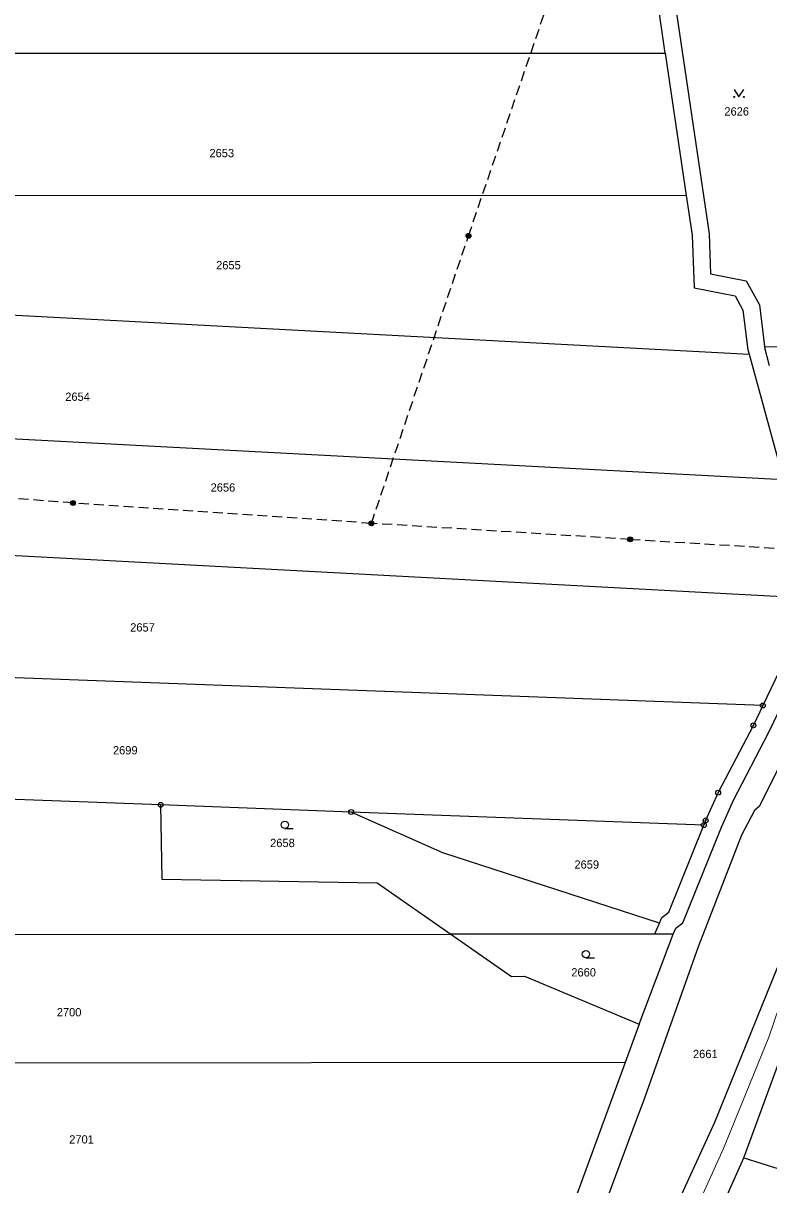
# Model space of a CAD drawing. Extents: x -606517 to -602431, y -1183120 to -1179397.
# Drawn here: x -605722.9 to -605569.9, y -1181000.2 to -1180761.6 of the extents above; entities that cross this region are included whole.
import ezdxf

# ---------------------------------------------------------------- set-up
doc = ezdxf.new("R2010")
doc.units = 0
doc.header["$LTSCALE"] = 0.68
doc.linetypes.add('MEDIUM_DASHED', pattern=[4.5, 3, -1.5])
for name, color, linetype, lineweight in [('1', 7, 'Continuous', 25), ('3', 7, 'Continuous', 25), ('4', 7, 'Continuous', 13), ('6', 7, 'Continuous', 25), ('8', 7, 'Continuous', 25)]:
    doc.layers.add(name, color=color, linetype=linetype, lineweight=lineweight)
doc.layers.add('2', color=7, linetype='Continuous')

msp = doc.modelspace()

# ---------------------------------------------------------------- linework, layer by layer
at = {"layer": '1'}
for p, q in [((-605591.11, -1180767.77), (-605594.1, -1180747.43)), ((-605590.7, -1180746.5), (-605582.12, -1180804.85)), ((-605748.69, -1180767.72), (-605591.11, -1180767.77)), ((-605591.11, -1180767.77), (-605586.81, -1180796.99)), ((-605751.61, -1180796.94), (-605586.81, -1180796.99)), ((-605586.81, -1180796.99), (-605585.61, -1180805.17)), ((-605582.12, -1180804.85), (-605581.81, -1180813.05)), ((-605585.61, -1180805.17), (-605585.2, -1180815.94)), ((-605581.81, -1180813.05), (-605574.5, -1180814.52)), ((-605574.5, -1180814.52), (-605571.79, -1180819.43)), ((-605585.2, -1180815.94), (-605576.78, -1180817.63)), ((-605576.78, -1180817.63), (-605575.18, -1180820.53)), ((-605754.37, -1180819.97), (-605573.91, -1180829.6)), ((-605575.18, -1180820.53), (-605574.16, -1180828.69)), ((-605571.79, -1180819.43), (-605570.72, -1180828.01)), ((-605574.16, -1180828.69), (-605573.91, -1180829.6)), ((-605569.74, -1180831.99), (-605570.72, -1180828.01)), ((-605570.72, -1180828.01), (-605551.72, -1180828.34)), ((-605573.91, -1180829.6), (-605566.84, -1180855.43)), ((-605566.84, -1180855.43), (-605757.45, -1180845.25)), ((-605759.74, -1180869.08), (-605560.54, -1180879.72)), ((-605569.88, -1180907.4), (-605555.9, -1180878.13)), ((-605560.54, -1180879.72), (-605571.07, -1180901.77)), ((-605571.07, -1180901.77), (-605762.19, -1180894.64)), ((-605571.07, -1180901.77), (-605573.01, -1180905.83)), ((-605573.01, -1180905.83), (-605580.25, -1180919.66)), ((-605577.1, -1180921.19), (-605569.88, -1180907.4)), ((-605563.54, -1180905.8), (-605571.77, -1180922.45)), ((-605694.69, -1180922.18), (-605764.72, -1180919.56)), ((-605580.25, -1180919.66), (-605582.81, -1180925.37)), ((-605579.59, -1180926.74), (-605577.1, -1180921.19)), ((-605694.69, -1180922.18), (-605694.45, -1180937.43)), ((-605655.59, -1180923.64), (-605694.69, -1180922.18)), ((-605583.2, -1180926.34), (-605655.59, -1180923.64)), ((-605636.78, -1180932.06), (-605655.59, -1180923.64)), ((-605572.78, -1180923.31), (-605575.47, -1180928.41)), ((-605571.77, -1180922.45), (-605572.78, -1180923.31)), ((-605590.36, -1180944.21), (-605583.2, -1180926.34)), ((-605582.81, -1180925.37), (-605583.2, -1180926.34)), ((-605587.47, -1180946.4), (-605579.59, -1180926.74)), ((-605575.47, -1180928.41), (-605584.32, -1180951.36)), ((-605592.28, -1180946.45), (-605636.78, -1180932.06)), ((-605694.45, -1180937.43), (-605650.27, -1180938.22)), ((-605650.27, -1180938.22), (-605635.12, -1180948.76)), ((-605592.28, -1180946.45), (-605591.78, -1180945.31)), ((-605591.78, -1180945.31), (-605590.36, -1180944.21)), ((-605593.24, -1180948.66), (-605592.28, -1180946.45)), ((-605589.45, -1180948.73), (-605588.93, -1180947.53)), ((-605588.93, -1180947.53), (-605587.47, -1180946.4)), ((-605769, -1180948.86), (-605635.12, -1180948.76)), ((-605616.86, -1180948.75), (-605635.12, -1180948.76)), ((-605635.12, -1180948.76), (-605622.68, -1180957.42)), ((-605593.27, -1180948.73), (-605616.86, -1180948.75)), ((-605596.43, -1180967.23), (-605589.45, -1180948.73)), ((-605593.27, -1180948.73), (-605593.24, -1180948.66)), ((-605589.45, -1180948.73), (-605593.27, -1180948.73)), ((-605584.32, -1180951.36), (-605595.65, -1180983.15)), ((-605622.68, -1180957.42), (-605620.02, -1180957.37)), ((-605620.02, -1180957.37), (-605596.43, -1180967.23)), ((-605580.95, -1180987.38), (-605568.09, -1180955.6)), ((-605596.43, -1180967.23), (-605599.33, -1180975.13)), ((-605574.98, -1180994.69), (-605566.34, -1180971.18)), ((-605599.33, -1180975.13), (-605772.93, -1180975.26)), ((-605599.33, -1180975.13), (-605609.21, -1181002.01)), ((-605595.65, -1180983.15), (-605596.9, -1180986.39)), ((-605596.9, -1180986.39), (-605609.67, -1181021.03)), ((-605595.15, -1181018.31), (-605580.95, -1180987.38)), ((-605580.12, -1181006.24), (-605574.98, -1180994.69)), ((-605574.98, -1180994.69), (-605553.1, -1181001.62))]:
    msp.add_line(p, q, dxfattribs=at)
at = {"layer": '3'}
for p, q in [((-605669.203, -1180927.02), (-605667.453, -1180927.02)), ((-605607.383, -1180953.6), (-605605.633, -1180953.6))]:
    msp.add_line(p, q, dxfattribs=at)
msp.add_lwpolyline([(-605576.97, -1180775.239), (-605575.97, -1180776.74), (-605574.97, -1180775.239)], dxfattribs=at)
for centre, radius in [((-605576.97, -1180776.7395), 0.1), ((-605574.97, -1180776.7395), 0.1), ((-605669.2029, -1180926.2698), 0.75), ((-605607.3829, -1180952.8498), 0.75)]:
    msp.add_circle(centre, radius, dxfattribs=at)
at = {"layer": '4'}
msp.add_lwpolyline([(-605616.4, -1181091.03), (-605616.44, -1181076.41), (-605608.98, -1181057.17), (-605603.42, -1181044.56), (-605595.68, -1181029.4), (-605579.16, -1180992.77), (-605569.81, -1180969.9), (-605559.25, -1180938.77), (-605553.42, -1180922.56)], dxfattribs=at)
at = {"layer": '6', "linetype": 'MEDIUM_DASHED'}
msp.add_line((-605598.29, -1180867.63), (-605558.05, -1180870.05), dxfattribs=at)
for points in [[(-605651.42, -1180864.34), (-605631.5, -1180805.27), (-605613.58, -1180752.72)], [(-605598.29, -1180867.63), (-605651.42, -1180864.34), (-605712.66, -1180860.16), (-605764.57, -1180856.2)]]:
    msp.add_lwpolyline(points, dxfattribs=at)
at = {"layer": '6'}
for centre, radius in [((-605631.5034, -1180805.2699), 0.5), ((-605631.5034, -1180805.2699), 0.4), ((-605631.5034, -1180805.2699), 0.3), ((-605631.5034, -1180805.2699), 0.2), ((-605631.5034, -1180805.2699), 0.1), ((-605712.6634, -1180860.1599), 0.5), ((-605712.6634, -1180860.1599), 0.4), ((-605712.6634, -1180860.1599), 0.3), ((-605712.6634, -1180860.1599), 0.2), ((-605712.6634, -1180860.1599), 0.1), ((-605651.4234, -1180864.3399), 0.5), ((-605651.4234, -1180864.3399), 0.4), ((-605651.4234, -1180864.3399), 0.3), ((-605651.4234, -1180864.3399), 0.2), ((-605651.4234, -1180864.3399), 0.1), ((-605598.2934, -1180867.6299), 0.5), ((-605598.2934, -1180867.6299), 0.4), ((-605598.2934, -1180867.6299), 0.3), ((-605598.2934, -1180867.6299), 0.2), ((-605598.2934, -1180867.6299), 0.1)]:
    msp.add_circle(centre, radius, dxfattribs=at)
at = {"layer": '8'}
for centre, radius in [((-605571.07, -1180901.7699), 0.5), ((-605571.07, -1180901.7699), 0.0303), ((-605573.01, -1180905.8299), 0.5), ((-605573.01, -1180905.8299), 0.0303), ((-605580.25, -1180919.6599), 0.5), ((-605694.69, -1180922.1799), 0.5), ((-605580.25, -1180919.6599), 0.0303), ((-605694.69, -1180922.1799), 0.0303), ((-605655.59, -1180923.6399), 0.5), ((-605655.59, -1180923.6399), 0.0303), ((-605583.2, -1180926.3399), 0.5), ((-605582.81, -1180925.3699), 0.5), ((-605583.2, -1180926.3399), 0.0303), ((-605582.81, -1180925.3699), 0.0303)]:
    msp.add_circle(centre, radius, dxfattribs=at)

# ---------------------------------------------------------------- texts
at = {"layer": '2'}
for s, p in [('2626', (-605578.97, -1180780.565)), ('2653', (-605684.67, -1180789.125)), ('2655', (-605683.3, -1180812.155)), ('2654', (-605714.27, -1180839.175)), ('2656', (-605684.43, -1180857.825)), ('2657', (-605700.94, -1180886.565)), ('2699', (-605704.48, -1180911.805)), ('2658', (-605672.21, -1180930.845)), ('2659', (-605609.75, -1180935.275)), ('2660', (-605610.39, -1180957.425)), ('2700', (-605716.01, -1180965.615)), ('2661', (-605585.41, -1180974.195)), ('2701', (-605713.46, -1180991.745))]:
    msp.add_text(s, height=1.7, dxfattribs=at).set_placement(p)

doc.saveas('drawing.dxf')
